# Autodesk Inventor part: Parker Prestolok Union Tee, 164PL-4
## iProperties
Shininess: 20.0
Length Units: 11272
Angle Units: 11279
Time Units: 11290
Mass Units: 11286
Length Display Precision: 3
Angle Display Precision: 2
Created: 2001-09
Part Number: Parker Prestolok Union Tee, 164PL-4
Material: Stainless Steel, Austenitic
Description: Parker Prestolok Union Tee, 164PL-4
Document SubType Name: Modeling
Designer: jhagarty
Density: 0.0
Volumn: 0.0
Area: 0.0
PropertySet Name: Model Information
Control State: 0
Master: False
Checked Out: False
Author: jhagarty
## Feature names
1. Extrusion1
2. Extrusion7
3. Extrusion8
4. Revolution7
5. Revolution8
6. Mirror3
7. Hole5
8. Extrusion9
9. Revolution9
10. Revolution10
11. Hole6
